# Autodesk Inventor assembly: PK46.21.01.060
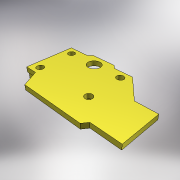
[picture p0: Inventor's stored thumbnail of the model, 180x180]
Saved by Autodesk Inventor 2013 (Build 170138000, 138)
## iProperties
Created: 2005-04
Part Number: PK46.21.01.060
Document SubType Name: Assembly
Designer: salex
Manufacturer: Standard
Standards Organization: Custom
Author: salex
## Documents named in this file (3)
- C:\Product Design Suite 2013 Test Drive\Dynamic Simulation\Workspace\Assy, Chassis, Front\PK46.21.01.060.iam
- C:\Product Design Suite 2013 Test Drive\Dynamic Simulation\Workspace\Assy, Chassis, Front\PK46.21.01.017.ipt
- C:\Product Design Suite 2013 Test Drive\Dynamic Simulation\Workspace\Assy, Chassis, Front\PK46.21.01.018.ipt
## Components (3 placed, 2 different names)
1. PK46.21.01.017:1 — Вставка:1, Совмещение:1, Вставка:2, Совмещение:2
2. PK46.21.01.018:1 — Вставка:2, Совмещение:2
3. PK46.21.01.018:2 — Вставка:1, Совмещение:1
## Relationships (4: Insert 2, Mate 2)
- Вставка:1 [Insert]: PK46.21.01.017:1 ↔ PK46.21.01.018:2
- Совмещение:1 [Mate]: PK46.21.01.017:1 ↔ PK46.21.01.018:2
- Вставка:2 [Insert]: PK46.21.01.017:1 ↔ PK46.21.01.018:1
- Совмещение:2 [Mate]: PK46.21.01.017:1 ↔ PK46.21.01.018:1
